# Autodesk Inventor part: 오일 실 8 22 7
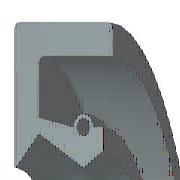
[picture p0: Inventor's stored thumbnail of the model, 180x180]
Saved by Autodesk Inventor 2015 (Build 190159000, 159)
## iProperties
IsCustomPart: 1
Created: 2012-02
Part Number: 오일 실 8 22 7
Material: 고무
Description: 오일-실
Document SubType Name: Modeling
Standard: KS B 2804
Designer: mduedu
Standards Organization: KS
Language: ko-KR
Size Designation: D - 8 22 7
Categories: <MemberInstance><Categories><Category DisplayName="샤프트 부품" InternalName="7f7aeb1f-a693-4053-b835-cee3144e0d98" Mnemonic="SHFT"><Category DisplayName="실링" Intern
Density: 0.93 g/cm^3
Appearance: 고무 - 검은색 - 버전 1.1
Mass: 1.28441 g
Surface Area: 18.2787 cm^2
Volume: 1.38108 cm^3
Author: mduedu
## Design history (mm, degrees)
revolve "본체" stored, may be unused: angle "d17" = 90 deg
revolve "스프링1" stored, may be unused: angle "d18" = 90 deg
body "Solid1"
sketch "스케치1"
  geometry: L1 (0, 11)-(7, 11); L2 (7, 9.25)-(1.75, 9.25); L3 (1.75, 5.75)-(4.9, 4); L4 (4.9, 4)-(0, 4); L5 (0, 0)-(9.586, 0) reference; L6 (4.9, 4)-(6.3, 4.875); L7 (0, 18)-(0, -3) reference; L8 (-1.941, 0)-(11.507, 0) reference; L9 (4.2, 6.1)-(1.75, 6.59); L10 (1.75, 6.59)-(1.75, 9.25); L11 (0, 11)-(0, 4.088); L12 (4.9, 4)-(0, 4); L13 (1.75, 5.75)-(0.152, 4.028); L14 (7, 11)-(7, 9.25); L15 (5.6, 6.1)-(6.3, 6.1); L16 (6.3, 6.1)-(6.3, 4.875); C1 r 0.455 at (4.9, 6.1); A1 r 0.7 centre (4.9, 6.1) between (5.6, 6.1) and (4.2, 6.1); A2 r 0.088 centre (0.088, 4.088) between (0, 4.088) and (0.152, 4.028); 1 further point
  constraints: 28 end point, 5 horizontal alignment, 5 point on line, 4 point on circle, 4 vertical alignment, 3 centre point, 3 tangent, 2 collinear, 2 horizontal, 2 perpendicular, 1 coincident, 1 parallel
  dimensions: "d0" = 22 diameter of L1 L5 (= SD2); "d1" = 1.75 distance of L1.end L2.start (= SD); "d2" = 0.91 diameter of C1 (= SPDI); "d3" = 1.4 diameter of A1 (= SPDA); "d4" = 8 diameter of L3.end L5 (= NND); "d5" = 11.5 diameter of L3.start L5 (= TKDM); "d7" = 13.18 diameter of L9.end L5 (= TKDM + 0.24 x SWDT); "d8" = 1.75 distance between parallel lines of L11 L10 (= SD); "d9" = 4.9 distance from line of L11 C1.centre (= SPDST); "d10" = 12.2 diameter of C1.centre L5 (= HLDM); "d11" = 0.0875 radius of A2 (= 0.25 x LAB); "d12" = 6.3 distance between parallel lines of L11 L16 (= SDI); "d13" = 9.75 diameter of L6.end L5 (= ABDM); "d14" = 7 distance from line of L11 L1.end (= SWDT)
fillet "모깎기1" dims "d6" = 0.3 (= RR)
other parameters: "SD2" = 22 [user parameter; used in 1 equation term], "SWDT" = 7 [user parameter; used in 2 equation terms], "RR" = 0.3 [user parameter; used in 1 equation term], "SD" = 1.75 [user parameter; used in 2 equation terms], "NND" = 8 [user parameter; used in 1 equation term], "SPDA" = 1.4 [user parameter; used in 1 equation term], "SPDI" = 0.91 [user parameter; used in 1 equation term], "TKDM" = 11.5 [user parameter; used in 2 equation terms], "HLDM" = 12.2 [user parameter; used in 1 equation term], "ABDM" = 9.75 [user parameter; used in 1 equation term], "SDI" = 6.3 [user parameter; used in 1 equation term], "SPDST" = 4.9 [user parameter; used in 1 equation term], "LAB" = 0.35 [user parameter; used in 1 equation term], "d15" = 0, "d16" = 0, "d19" = 0
